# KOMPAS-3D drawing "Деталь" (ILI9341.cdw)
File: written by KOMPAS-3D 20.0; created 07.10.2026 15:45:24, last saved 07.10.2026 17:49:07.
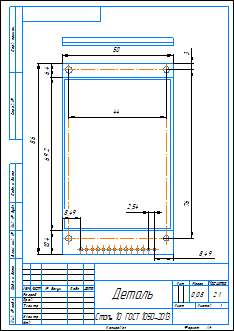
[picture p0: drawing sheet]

Sheet 1: A4, portrait

Document properties: Масса: 0.0790697

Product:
- Part/product: Деталь
    Масса: 0.0790697
  - Body: Тело 1
      Масса: 0.10441

Title block, sheet 1: Наименование: Деталь; Материал: Сталь 10  ГОСТ 1050-2013; Масса: 0,08; Количество листов документа: 1; Форматы листов документа: A4; stored path: D:\myProjects\Progect_esp32\box_compas\ILI9341.cdw

Views: Вид 1, Спереди, Проекционный вид 2
Referenced files in D:\myProjects\Progect_esp32\box_compas\: ILI9341.m3d
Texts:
  Линейный размер
Dimensions and other numbers on the sheet: 86; 50; 76; 3; 6,4; 69,2; 10,4; 8,49; 44; 2,54; 2:1; 1; 0,08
